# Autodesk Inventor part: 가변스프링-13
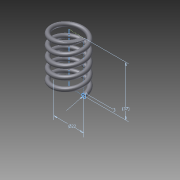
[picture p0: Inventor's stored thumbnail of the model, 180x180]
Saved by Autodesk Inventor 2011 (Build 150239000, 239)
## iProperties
Created: 2015-05
Part Number: 가변스프링-13
Material: 탄소강
Document SubType Name: Modeling
Designer: Administrator
Mass: 19.2243 g
Surface Area: 32.8046 cm^2
Volume: 2.44273 cm^3
Density: 7.87 g/cm^3
Author: Administrator
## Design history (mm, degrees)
sketch "스케치1"
  geometry: L1 (0, 0)-(-11, 0); L2 (-11, 0)-(-11, 36.411); L3 (-11, 36.411)-(0, 36.411); L4 (0, 36.411)-(0, 0); C1 r 1.5 at (-11, 0)
  constraints: 8 end point, 2 parallel, 1 centre point, 1 coincident, 1 horizontal, 1 perpendicular
  dimensions: "d0" = 3 diameter of C1; "d1" = 22 diameter of L2 L4; "d2" = 36.4112 distance of L1.end L2.end (derived)
feature "코일1" sketch "스케치1" pitch "d3" = 10; turns "d5" = 5; dims "d4" = 36.4112 (= d2), "d6" = 0, angle "d7" = 90 deg, angle "d8" = 90 deg, "d9" = 0, "d10" = 0
node "작업 평면1"
sketch "스케치2"
  geometry: L1 (3, 0)-(0, 0) reference; 1 further point
  constraints: 1 horizontal alignment
extrude "돌출1" cut sketch "스케치2" distance "d11" = 10; taper "d12" = 0 deg
node "작업 평면2"
sketch "스케치3"
  geometry: L1 (0, 0)-(3, 0) reference; 1 further point
  constraints: 1 horizontal alignment
extrude "돌출2" cut sketch "스케치3" distance "d13" = 10; taper "d14" = 0 deg
node "솔리드1"
node "절단 모서리 투영1"
node "절단 모서리 투영2"
